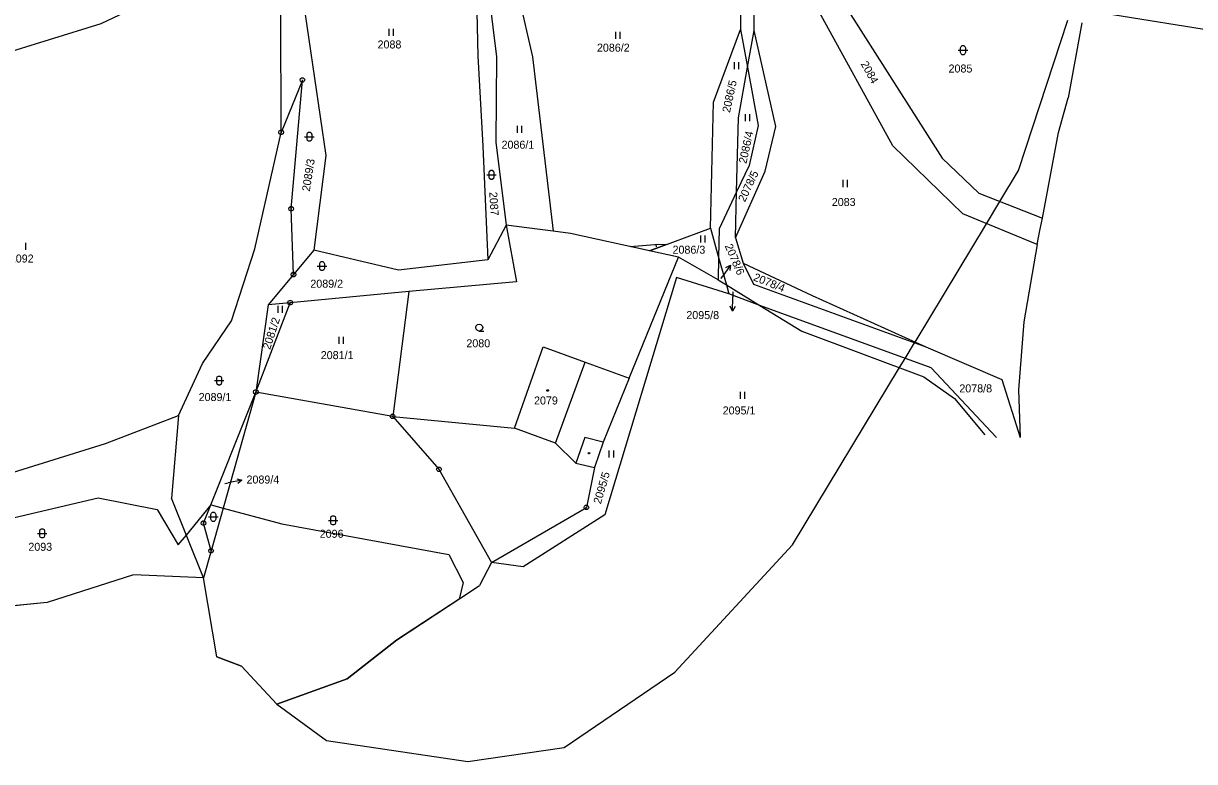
# Model space of a CAD drawing. Extents: x -806774 to -803680, y -1151731 to -1150053.
# Drawn here: x -804923.9 to -804675.1, y -1150761.5 to -1150604.7 of the extents above; entities that cross this region are included whole.
import ezdxf

# ---------------------------------------------------------------- set-up
doc = ezdxf.new("R2010")
doc.units = 0
for name, color, linetype in [('1', 7, 'Continuous'), ('11', 7, 'Continuous'), ('12', 7, 'Continuous'), ('13', 7, 'Continuous'), ('2', 7, 'Continuous'), ('3', 7, 'Continuous'), ('4', 7, 'Continuous'), ('5', 7, 'Continuous'), ('7', 7, 'Continuous'), ('8', 7, 'Continuous')]:
    doc.layers.add(name, color=color, linetype=linetype)

msp = doc.modelspace()

# ---------------------------------------------------------------- linework, layer by layer
at = {"layer": '1'}
for p, q in [((-804771.91, -1150579.38), (-804771.55, -1150606.03)), ((-804768.69, -1150606.23), (-804768.67, -1150582.3)), ((-804827.95, -1150589.7), (-804827.34, -1150611.64)), ((-804826.08, -1150589.72), (-804823.4, -1150611.86)), ((-804820.76, -1150589.98), (-804815.75, -1150611.81)), ((-804889.34, -1150596.17), (-804907.43, -1150604.85)), ((-804864.48, -1150599.92), (-804859.64, -1150632.81)), ((-804750.12, -1150599.8), (-804728.74, -1150633.39)), ((-804869.15, -1150627.88), (-804869.21, -1150602.7)), ((-804739.17, -1150630.73), (-804754.83, -1150602.27)), ((-804653.81, -1150609.12), (-804694.22, -1150602.66)), ((-804907.43, -1150604.85), (-804929.98, -1150611.77)), ((-804699.05, -1150604.64), (-804701.95, -1150620.52)), ((-804777.28, -1150621.47), (-804771.55, -1150606.03)), ((-804771.55, -1150606.03), (-804770.08, -1150614.03)), ((-804770.08, -1150614.03), (-804768.69, -1150606.23)), ((-804764.08, -1150626.66), (-804768.69, -1150606.23)), ((-804827.34, -1150611.64), (-804826.34, -1150630.79)), ((-804823.4, -1150611.86), (-804823.52, -1150629.98)), ((-804815.75, -1150611.81), (-804811.35, -1150648.88)), ((-804772, -1150624.77), (-804770.08, -1150614.03)), ((-804770.08, -1150614.03), (-804767.81, -1150626.42)), ((-804864.64, -1150616.76), (-804869.15, -1150627.88)), ((-804867.02, -1150644.1), (-804864.64, -1150616.76)), ((-804703.99, -1150627.92), (-804701.95, -1150620.52)), ((-804777.97, -1150648.22), (-804777.28, -1150621.47)), ((-804772.4, -1150640.49), (-804772, -1150624.77)), ((-804874.75, -1150652.58), (-804869.15, -1150627.88)), ((-804767.81, -1150626.42), (-804769.75, -1150634.89)), ((-804766.31, -1150636.13), (-804764.08, -1150626.66)), ((-804707.41, -1150646.12), (-804703.99, -1150627.92)), ((-804823.52, -1150629.98), (-804821.35, -1150647.6)), ((-804724.3, -1150645.21), (-804739.17, -1150630.73)), ((-804859.64, -1150632.81), (-804862.2, -1150652.87)), ((-804826.34, -1150630.79), (-804825.26, -1150654.97)), ((-804769.75, -1150634.89), (-804772.4, -1150640.49)), ((-804728.74, -1150633.39), (-804720.96, -1150640.79)), ((-804772.65, -1150650.27), (-804766.31, -1150636.13)), ((-804772.4, -1150640.49), (-804776.13, -1150648.36)), ((-804772.65, -1150650.27), (-804772.4, -1150640.49)), ((-804720.96, -1150640.79), (-804707.41, -1150646.12)), ((-804866.54, -1150658.07), (-804867.02, -1150644.1)), ((-804708.53, -1150651.71), (-804724.3, -1150645.21)), ((-804821.35, -1150647.6), (-804825.26, -1150654.97)), ((-804821.35, -1150647.6), (-804819.15, -1150659.64)), ((-804814.2, -1150648.52), (-804821.35, -1150647.6)), ((-804707.94, -1150648.75), (-804707.41, -1150646.12)), ((-804811.35, -1150648.88), (-804814.2, -1150648.52)), ((-804807.65, -1150649.35), (-804811.35, -1150648.88)), ((-804790.9, -1150653.05), (-804807.65, -1150649.35)), ((-804790.9, -1150653.05), (-804777.97, -1150648.22)), ((-804777.97, -1150648.22), (-804776.22, -1150654.42)), ((-804776.13, -1150648.36), (-804776.22, -1150654.42)), ((-804772.65, -1150650.27), (-804770.97, -1150655.66)), ((-804708.53, -1150651.71), (-804707.94, -1150648.75)), ((-804879.7, -1150667.88), (-804874.75, -1150652.58)), ((-804862.2, -1150652.87), (-804866.54, -1150658.07)), ((-804844.22, -1150657.16), (-804862.2, -1150652.87)), ((-804784.74, -1150654.41), (-804790.9, -1150653.05)), ((-804708.53, -1150651.71), (-804711.38, -1150668.12)), ((-804825.26, -1150654.97), (-804844.22, -1150657.16)), ((-804795.2, -1150680.11), (-804784.74, -1150654.41)), ((-804776.29, -1150659.21), (-804784.74, -1150654.41)), ((-804776.22, -1150654.42), (-804776.29, -1150659.21)), ((-804776.22, -1150654.42), (-804774.57, -1150660.26)), ((-804866.54, -1150658.07), (-804871.89, -1150664.5)), ((-804770.97, -1150655.66), (-804768.81, -1150660.09)), ((-804770.97, -1150655.66), (-804756.36, -1150662.51)), ((-804819.15, -1150659.64), (-804842, -1150661.64)), ((-804785.19, -1150658.73), (-804800.42, -1150709.08)), ((-804774.02, -1150662.2), (-804785.19, -1150658.73)), ((-804776.29, -1150659.21), (-804774.57, -1150660.26)), ((-804774.57, -1150660.26), (-804774.02, -1150662.2)), ((-804774.57, -1150660.26), (-804767.43, -1150664.63)), ((-804768.81, -1150660.09), (-804732.18, -1150673.45)), ((-804842, -1150661.64), (-804867.23, -1150664.05)), ((-804842, -1150661.64), (-804845.45, -1150688.21)), ((-804767.43, -1150664.63), (-804774.02, -1150662.2)), ((-804756.36, -1150662.51), (-804732.18, -1150673.45)), ((-804874.53, -1150683.02), (-804867.23, -1150664.05)), ((-804871.89, -1150664.5), (-804874.53, -1150683.02)), ((-804867.23, -1150664.05), (-804871.89, -1150664.5)), ((-804731.09, -1150677.9), (-804767.43, -1150664.63)), ((-804767.43, -1150664.63), (-804758.54, -1150670.07)), ((-804885.87, -1150676.95), (-804879.7, -1150667.88)), ((-804758.54, -1150670.07), (-804732.61, -1150679.77)), ((-804711.38, -1150668.12), (-804712.51, -1150682.53)), ((-804819.58, -1150690.67), (-804813.46, -1150673.44)), ((-804813.46, -1150673.44), (-804804.59, -1150676.68)), ((-804732.18, -1150673.45), (-804716.04, -1150680.35)), ((-804890.98, -1150688.02), (-804885.87, -1150676.95)), ((-804804.59, -1150676.68), (-804795.2, -1150680.11)), ((-804731.09, -1150677.9), (-804717.21, -1150692.67)), ((-804795.2, -1150680.11), (-804800.71, -1150693.66)), ((-804732.61, -1150679.77), (-804726.11, -1150684.37)), ((-804716.04, -1150680.35), (-804712.13, -1150692.67)), ((-804712.51, -1150682.53), (-804712.13, -1150692.67)), ((-804885.64, -1150710.87), (-804874.53, -1150683.02)), ((-804874.53, -1150683.02), (-804884.04, -1150716.73)), ((-804845.45, -1150688.21), (-804874.53, -1150683.02)), ((-804726.11, -1150684.37), (-804719.67, -1150692.12)), ((-804906.46, -1150693.95), (-804890.98, -1150688.02)), ((-804890.98, -1150688.02), (-804892.43, -1150705.53)), ((-804845.45, -1150688.21), (-804835.62, -1150699.43)), ((-804845.45, -1150688.21), (-804819.58, -1150690.67)), ((-804934.05, -1150702.55), (-804906.46, -1150693.95)), ((-804800.71, -1150693.66), (-804802.56, -1150699.04)), ((-804835.62, -1150699.43), (-804824.44, -1150719.23)), ((-804802.56, -1150699.04), (-804804.3, -1150707.53)), ((-804885.65, -1150722.45), (-804892.43, -1150705.53)), ((-804824.44, -1150719.23), (-804804.3, -1150707.53)), ((-804800.42, -1150709.08), (-804817.74, -1150720.13)), ((-804884.04, -1150716.73), (-804885.64, -1150710.87)), ((-804884.04, -1150716.73), (-804885.65, -1150722.45)), ((-804824.44, -1150719.23), (-804827.01, -1150724.13)), ((-804817.74, -1150720.13), (-804824.44, -1150719.23)), ((-804900.55, -1150721.82), (-804918.89, -1150727.72)), ((-804885.65, -1150722.45), (-804900.55, -1150721.82)), ((-804882.85, -1150739.24), (-804885.65, -1150722.45)), ((-804830.98, -1150726.73), (-804827.01, -1150724.13)), ((-804918.89, -1150727.72), (-804934.11, -1150729.21)), ((-804844.65, -1150735.69), (-804830.98, -1150726.73)), ((-804855.14, -1150743.91), (-804844.65, -1150735.69)), ((-804882.85, -1150739.24), (-804877.6, -1150741.26)), ((-804877.6, -1150741.26), (-804870.09, -1150749.31)), ((-804870.09, -1150749.31), (-804855.14, -1150743.91))]:
    msp.add_line(p, q, dxfattribs=at)
at = {"layer": '11'}
for points in [[(-804870.09, -1150749.31), (-804859.5, -1150757), (-804829.5, -1150761.5), (-804809, -1150758.5), (-804785.5, -1150742.5), (-804760.5, -1150715.5), (-804737.76, -1150677.84), (-804736.59, -1150675.89), (-804734.58, -1150672.57), (-804734.48, -1150672.41), (-804719.3, -1150647.27), (-804716.46, -1150642.56), (-804712.5, -1150636), (-804702, -1150604.05)], [(-804964.5, -1150712), (-804948.5, -1150715), (-804908, -1150705.5), (-804895.5, -1150708), (-804891, -1150715.5), (-804889.27, -1150713.4), (-804884, -1150707), (-804881.48, -1150707.67), (-804869, -1150711), (-804833.5, -1150717.5), (-804830.5, -1150723.5), (-804831.37, -1150726.99), (-804844.65, -1150735.69), (-804855.14, -1150743.91), (-804870.09, -1150749.31)], [(-804870.09, -1150749.31), (-804877.6, -1150741.26), (-804882.85, -1150739.24), (-804885.65, -1150722.45), (-804900.55, -1150721.82), (-804918.89, -1150727.72), (-804934.11, -1150729.21), (-804941.58, -1150726.61)]]:
    msp.add_lwpolyline(points, dxfattribs=at)
at = {"layer": '12'}
for p, q in [((-804819.58, -1150690.67), (-804813.46, -1150673.44)), ((-804813.46, -1150673.44), (-804804.59, -1150676.68)), ((-804810.87, -1150693.89), (-804804.59, -1150676.68)), ((-804810.87, -1150693.89), (-804819.58, -1150690.67))]:
    msp.add_line(p, q, dxfattribs=at)
at = {"layer": '13'}
for p, q in [((-804795.03, -1150652.14), (-804788.92, -1150651.64)), ((-804790.9, -1150653.05), (-804795.03, -1150652.14)), ((-804787.32, -1150651.71), (-804790.9, -1150653.05)), ((-804789.55, -1150651.69), (-804789.51, -1150652.19)), ((-804788.92, -1150651.64), (-804787.32, -1150651.71))]:
    msp.add_line(p, q, dxfattribs=at)
at = {"layer": '3'}
for p, q in [((-804846.27, -1150605.86), (-804846.27, -1150607.36)), ((-804845.27, -1150607.36), (-804845.27, -1150605.86)), ((-804798.14, -1150606.54), (-804798.14, -1150608.04)), ((-804797.14, -1150608.04), (-804797.14, -1150606.54)), ((-804772.94, -1150612.95), (-804772.94, -1150614.45)), ((-804771.94, -1150614.45), (-804771.94, -1150612.95)), ((-804770.6, -1150623.98), (-804770.6, -1150625.48)), ((-804769.6, -1150625.48), (-804769.6, -1150623.98)), ((-804819.01, -1150626.46), (-804819.01, -1150627.96)), ((-804818.01, -1150627.96), (-804818.01, -1150626.46)), ((-804749.85, -1150637.99), (-804749.85, -1150639.49)), ((-804748.85, -1150639.49), (-804748.85, -1150637.99)), ((-804780.07, -1150649.77), (-804780.07, -1150651.27)), ((-804779.07, -1150651.27), (-804779.07, -1150649.77)), ((-804923.38, -1150652.82), (-804923.38, -1150651.32)), ((-804869.87, -1150664.71), (-804869.87, -1150666.21)), ((-804868.87, -1150666.21), (-804868.87, -1150664.71)), ((-804856.89, -1150671.32), (-804856.89, -1150672.82)), ((-804855.89, -1150672.82), (-804855.89, -1150671.32)), ((-804771.67, -1150682.97), (-804771.67, -1150684.47)), ((-804770.67, -1150684.47), (-804770.67, -1150682.97)), ((-804799.51, -1150695.41), (-804799.51, -1150696.91)), ((-804798.51, -1150696.91), (-804798.51, -1150695.41))]:
    msp.add_line(p, q, dxfattribs=at)
for points in [[(-804725.3, -1150610.43), (-804724.03, -1150610.43), (-804723.3, -1150610.43)], [(-804864.16, -1150628.8), (-804862.89, -1150628.8), (-804862.16, -1150628.8)], [(-804825.47, -1150636.89), (-804824.2, -1150636.89), (-804823.47, -1150636.89)], [(-804861.47, -1150656.27), (-804860.2, -1150656.27), (-804859.47, -1150656.27)], [(-804827.06, -1150670.07), (-804827.44, -1150669.97), (-804827.71, -1150669.7), (-804827.81, -1150669.33), (-804827.71, -1150668.96), (-804827.44, -1150668.69), (-804827.07, -1150668.59), (-804826.7, -1150668.69), (-804826.43, -1150668.96), (-804826.33, -1150669.34), (-804826.43, -1150669.72), (-804826.7, -1150669.99), (-804827.08, -1150670.09), (-804826.08, -1150670.09)], [(-804883.32, -1150680.59), (-804882.05, -1150680.59), (-804881.32, -1150680.59)], [(-804884.56, -1150709.52), (-804883.29, -1150709.52), (-804882.56, -1150709.52)], [(-804859.12, -1150710.27), (-804857.85, -1150710.27), (-804857.12, -1150710.27)], [(-804920.93, -1150713.04), (-804919.66, -1150713.04), (-804918.93, -1150713.04)]]:
    msp.add_lwpolyline(points, dxfattribs=at)
for points in [[(-804724.8, -1150609.93), (-804724.7, -1150609.64), (-804724.45, -1150609.46), (-804724.14, -1150609.46), (-804723.89, -1150609.64), (-804723.79, -1150609.93), (-804723.79, -1150610.93), (-804723.89, -1150611.22), (-804724.14, -1150611.4), (-804724.45, -1150611.4), (-804724.7, -1150611.22), (-804724.8, -1150610.93)], [(-804863.66, -1150628.3), (-804863.56, -1150628.01), (-804863.31, -1150627.83), (-804863, -1150627.83), (-804862.75, -1150628.01), (-804862.65, -1150628.3), (-804862.65, -1150629.3), (-804862.75, -1150629.59), (-804863, -1150629.77), (-804863.31, -1150629.77), (-804863.56, -1150629.59), (-804863.66, -1150629.3)], [(-804824.97, -1150636.39), (-804824.87, -1150636.1), (-804824.62, -1150635.92), (-804824.31, -1150635.92), (-804824.06, -1150636.1), (-804823.96, -1150636.39), (-804823.96, -1150637.39), (-804824.06, -1150637.68), (-804824.31, -1150637.86), (-804824.62, -1150637.86), (-804824.87, -1150637.68), (-804824.97, -1150637.39)], [(-804860.97, -1150655.77), (-804860.87, -1150655.48), (-804860.62, -1150655.3), (-804860.31, -1150655.3), (-804860.06, -1150655.48), (-804859.96, -1150655.77), (-804859.96, -1150656.77), (-804860.06, -1150657.06), (-804860.31, -1150657.24), (-804860.62, -1150657.24), (-804860.87, -1150657.06), (-804860.97, -1150656.77)], [(-804882.82, -1150680.09), (-804882.72, -1150679.8), (-804882.47, -1150679.62), (-804882.16, -1150679.62), (-804881.91, -1150679.8), (-804881.81, -1150680.09), (-804881.81, -1150681.09), (-804881.91, -1150681.38), (-804882.16, -1150681.56), (-804882.47, -1150681.56), (-804882.72, -1150681.38), (-804882.82, -1150681.09)], [(-804884.06, -1150709.02), (-804883.96, -1150708.73), (-804883.71, -1150708.55), (-804883.4, -1150708.55), (-804883.15, -1150708.73), (-804883.05, -1150709.02), (-804883.05, -1150710.02), (-804883.15, -1150710.31), (-804883.4, -1150710.49), (-804883.71, -1150710.49), (-804883.96, -1150710.31), (-804884.06, -1150710.02)], [(-804858.62, -1150709.77), (-804858.52, -1150709.48), (-804858.27, -1150709.3), (-804857.96, -1150709.3), (-804857.71, -1150709.48), (-804857.61, -1150709.77), (-804857.61, -1150710.77), (-804857.71, -1150711.06), (-804857.96, -1150711.24), (-804858.27, -1150711.24), (-804858.52, -1150711.06), (-804858.62, -1150710.77)], [(-804920.43, -1150712.54), (-804920.33, -1150712.25), (-804920.08, -1150712.07), (-804919.77, -1150712.07), (-804919.52, -1150712.25), (-804919.42, -1150712.54), (-804919.42, -1150713.54), (-804919.52, -1150713.83), (-804919.77, -1150714.01), (-804920.08, -1150714.01), (-804920.33, -1150713.83), (-804920.43, -1150713.54)]]:
    msp.add_lwpolyline(points, close=True, dxfattribs=at)
at = {"layer": '4'}
for p, q in [((-804810.87, -1150693.89), (-804804.59, -1150676.68)), ((-804810.87, -1150693.89), (-804819.58, -1150690.67)), ((-804804.63, -1150692.65), (-804806.56, -1150698.11)), ((-804800.71, -1150693.66), (-804804.63, -1150692.65)), ((-804806.56, -1150698.11), (-804810.87, -1150693.89)), ((-804806.56, -1150698.11), (-804802.56, -1150699.04))]:
    msp.add_line(p, q, dxfattribs=at)
at = {"layer": '5'}
for points in [[(-804812.54, -1150682.53), (-804812.44, -1150682.55), (-804812.39, -1150682.64), (-804812.37, -1150682.7), (-804812.39, -1150682.79), (-804812.47, -1150682.86), (-804812.54, -1150682.87), (-804812.63, -1150682.84), (-804812.69, -1150682.78), (-804812.71, -1150682.7), (-804812.69, -1150682.61), (-804812.61, -1150682.54)], [(-804803.66, -1150695.87), (-804803.57, -1150696.02), (-804803.66, -1150696.17), (-804803.84, -1150696.17), (-804803.93, -1150696.02), (-804803.84, -1150695.87)]]:
    msp.add_lwpolyline(points, close=True, dxfattribs=at)
at = {"layer": '7'}
for p, q in [((-804773.69, -1150656.08), (-804775.43, -1150658.53)), ((-804775.7, -1150658.91), (-804775.43, -1150658.53)), ((-804773.25, -1150665.83), (-804773.19, -1150662.83)), ((-804773.17, -1150661.74), (-804773.19, -1150662.83)), ((-804881.14, -1150702.45), (-804880.44, -1150702.32)), ((-804877.49, -1150701.75), (-804880.44, -1150702.32))]:
    msp.add_line(p, q, dxfattribs=at)
for points in [[(-804774.68, -1150656.61), (-804773.69, -1150656.08), (-804773.86, -1150657.19)], [(-804772.73, -1150664.84), (-804773.25, -1150665.83), (-804773.73, -1150664.82)], [(-804878.57, -1150701.45), (-804877.49, -1150701.75), (-804878.38, -1150702.43)]]:
    msp.add_lwpolyline(points, dxfattribs=at)
at = {"layer": '8'}
for p, q in [((-804864.76, -1150616.76), (-804864.52, -1150616.76)), ((-804869.27, -1150627.88), (-804869.03, -1150627.88)), ((-804867.14, -1150644.1), (-804866.9, -1150644.1)), ((-804866.66, -1150658.07), (-804866.42, -1150658.07)), ((-804867.35, -1150664.05), (-804867.11, -1150664.05)), ((-804874.65, -1150683.02), (-804874.41, -1150683.02)), ((-804845.57, -1150688.21), (-804845.33, -1150688.21)), ((-804835.74, -1150699.43), (-804835.5, -1150699.43)), ((-804804.42, -1150707.53), (-804804.18, -1150707.53)), ((-804885.76, -1150710.87), (-804885.52, -1150710.87)), ((-804884.16, -1150716.73), (-804883.92, -1150716.73))]:
    msp.add_line(p, q, dxfattribs=at)
for points in [[(-804864.49, -1150616.28), (-804864.24, -1150616.46), (-804864.14, -1150616.75), (-804864.24, -1150617.04), (-804864.49, -1150617.22), (-804864.8, -1150617.22), (-804865.05, -1150617.04), (-804865.15, -1150616.75), (-804865.05, -1150616.46), (-804864.8, -1150616.28)], [(-804869, -1150627.4), (-804868.75, -1150627.58), (-804868.65, -1150627.87), (-804868.75, -1150628.16), (-804869, -1150628.34), (-804869.31, -1150628.34), (-804869.56, -1150628.16), (-804869.66, -1150627.87), (-804869.56, -1150627.58), (-804869.31, -1150627.4)], [(-804866.87, -1150643.62), (-804866.62, -1150643.8), (-804866.52, -1150644.09), (-804866.62, -1150644.38), (-804866.87, -1150644.56), (-804867.18, -1150644.56), (-804867.43, -1150644.38), (-804867.53, -1150644.09), (-804867.43, -1150643.8), (-804867.18, -1150643.62)], [(-804866.39, -1150657.59), (-804866.14, -1150657.77), (-804866.04, -1150658.06), (-804866.14, -1150658.35), (-804866.39, -1150658.53), (-804866.7, -1150658.53), (-804866.95, -1150658.35), (-804867.05, -1150658.06), (-804866.95, -1150657.77), (-804866.7, -1150657.59)], [(-804867.08, -1150663.57), (-804866.83, -1150663.75), (-804866.73, -1150664.04), (-804866.83, -1150664.33), (-804867.08, -1150664.51), (-804867.39, -1150664.51), (-804867.64, -1150664.33), (-804867.74, -1150664.04), (-804867.64, -1150663.75), (-804867.39, -1150663.57)], [(-804874.38, -1150682.54), (-804874.13, -1150682.72), (-804874.03, -1150683.01), (-804874.13, -1150683.3), (-804874.38, -1150683.48), (-804874.69, -1150683.48), (-804874.94, -1150683.3), (-804875.04, -1150683.01), (-804874.94, -1150682.72), (-804874.69, -1150682.54)], [(-804845.3, -1150687.73), (-804845.05, -1150687.91), (-804844.95, -1150688.2), (-804845.05, -1150688.49), (-804845.3, -1150688.67), (-804845.61, -1150688.67), (-804845.86, -1150688.49), (-804845.96, -1150688.2), (-804845.86, -1150687.91), (-804845.61, -1150687.73)], [(-804835.47, -1150698.95), (-804835.22, -1150699.13), (-804835.12, -1150699.42), (-804835.22, -1150699.71), (-804835.47, -1150699.89), (-804835.78, -1150699.89), (-804836.03, -1150699.71), (-804836.13, -1150699.42), (-804836.03, -1150699.13), (-804835.78, -1150698.95)], [(-804804.15, -1150707.05), (-804803.9, -1150707.23), (-804803.8, -1150707.52), (-804803.9, -1150707.81), (-804804.15, -1150707.99), (-804804.46, -1150707.99), (-804804.71, -1150707.81), (-804804.81, -1150707.52), (-804804.71, -1150707.23), (-804804.46, -1150707.05)], [(-804885.49, -1150710.39), (-804885.24, -1150710.57), (-804885.14, -1150710.86), (-804885.24, -1150711.15), (-804885.49, -1150711.33), (-804885.8, -1150711.33), (-804886.05, -1150711.15), (-804886.15, -1150710.86), (-804886.05, -1150710.57), (-804885.8, -1150710.39)], [(-804883.89, -1150716.25), (-804883.64, -1150716.43), (-804883.54, -1150716.72), (-804883.64, -1150717.01), (-804883.89, -1150717.19), (-804884.2, -1150717.19), (-804884.45, -1150717.01), (-804884.55, -1150716.72), (-804884.45, -1150716.43), (-804884.2, -1150716.25)]]:
    msp.add_lwpolyline(points, close=True, dxfattribs=at)

# ---------------------------------------------------------------- texts
at = {"layer": '2'}
for s, height, p in [('2088', 1.7, (-804848.67, -1150610.06)), ('2086/2', 1.7, (-804802.06, -1150610.74)), ('2085', 1.7, (-804727.36, -1150615.17)), ('2086/1', 1.7, (-804822.33, -1150631.35)), ('2083', 1.7, (-804752.17, -1150643.52)), ('2086/3', 1.7, (-804786, -1150653.65)), ('2092', 1.7, (-804926.8, -1150655.52)), ('2089/2', 1.7, (-804862.95, -1150660.87)), ('2078/6', 0.1, (-804775.95, -1150658.91)), ('2095/8', 0.1, (-804773.42, -1150661.74)), ('2080', 1.7, (-804829.8, -1150673.52)), ('2081/1', 1.7, (-804860.74, -1150676.04)), ('2078/8', 1.7, (-804725.07, -1150683.1)), ('2089/1', 1.7, (-804886.68, -1150684.94)), ('2079', 1.7, (-804815.43, -1150685.67)), ('2095/1', 1.7, (-804775.35, -1150687.78)), ('2089/4', 0.1, (-804881.13, -1150702.45)), ('2096', 1.7, (-804860.96, -1150713.97)), ('2093', 1.7, (-804922.86, -1150716.74))]:
    msp.add_text(s, height=height, dxfattribs=at).set_placement(p)
for s, rotation, p in [('2084', 299.084, (-804746.09, -1150613.31)), ('2086/5', 77.5785, (-804773.82, -1150623.8)), ('2086/4', 77.4639, (-804770.32, -1150634.62)), ('2089/3', 81.0162, (-804863.08, -1150640.5)), ('2078/5', 64.8588, (-804770.62, -1150642.8)), ('2087', 273.7019, (-804824.95, -1150640.58)), ('2078/4', 338.1024, (-804768.98, -1150659.27)), ('2081/2', 72.0208, (-804871.52, -1150674.12)), ('2095/5', 73.6251, (-804801.24, -1150706.93))]:
    msp.add_text(s, height=1.7, rotation=rotation, dxfattribs=at).set_placement(p)
at = {"layer": '7'}
msp.add_text('2078/6', height=1.7, rotation=293.2971, dxfattribs=at).set_placement((-804774.94, -1150651.99))
for s, p in [('2095/8', (-804783.07, -1150667.53)), ('2089/4', (-804876.51, -1150702.46))]:
    msp.add_text(s, height=1.7, dxfattribs=at).set_placement(p)

doc.saveas('drawing.dxf')
